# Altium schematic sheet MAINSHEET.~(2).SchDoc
size 594 x 420 mm; Scale: 1:1; Разраб.: Иванов; Обозначение документа: АБВГ.123456.001 Э3; Пров.: Петров; Утв.: Сидоров; Наименование организации: ОАО "Концерн "МПО-Гидроприбор"; Перв. применение: АБВГ.123456.000; Наименование изделия 1: Плата; Наименование изделия 2: Схема электрическая; Наименование изделия 3: принципиальная; Нач. отд.: Нач. отд.; Фамилия нач. отд.: Сидоров
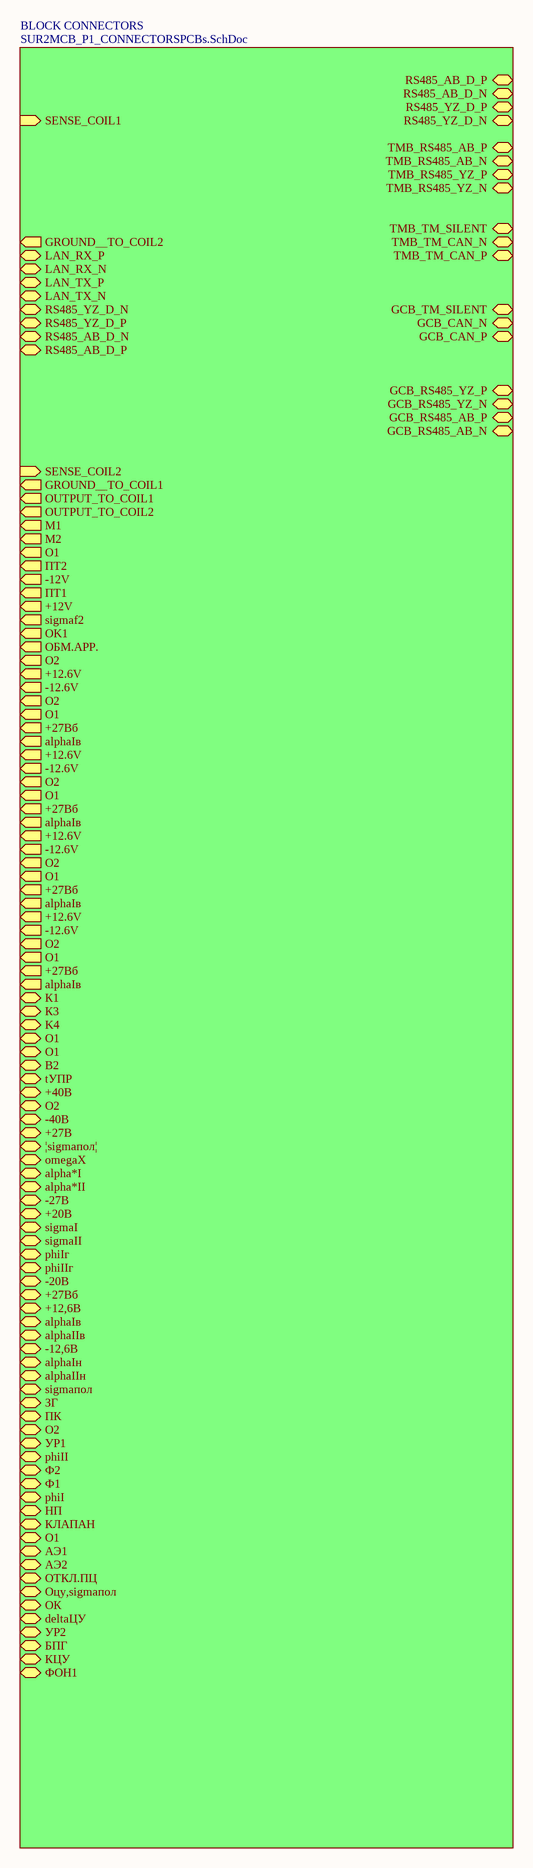
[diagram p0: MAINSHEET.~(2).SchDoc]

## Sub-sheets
BLOCK CONNECTORS = SUR2MCB_P1_CONNECTORSPCBs.SchDoc: RS485_AB_D_P (bidir), RS485_AB_D_N (bidir), SENSE_COIL1 (in), RS485_YZ_D_P (bidir), RS485_YZ_D_N (bidir), TMB_RS485_AB_P (bidir), TMB_TM_SILENT (bidir), TMB_TM_CAN_N (bidir), TMB_RS485_AB_N (bidir), GCB_CAN_N (bidir), GCB_TM_SILENT (bidir), GROUND__TO_COIL2 (out), LAN_RX_P (bidir), LAN_RX_N (bidir), LAN_TX_P (bidir), LAN_TX_N (bidir), RS485_YZ_D_N (bidir), RS485_YZ_D_P (bidir), RS485_AB_D_N (bidir), RS485_AB_D_P (bidir), GCB_CAN_P (bidir), GCB_RS485_YZ_N (bidir), TMB_TM_CAN_P (bidir), GCB_RS485_AB_P (bidir), TMB_RS485_YZ_P (bidir), TMB_RS485_YZ_N (bidir), GCB_RS485_YZ_P (bidir), GCB_RS485_AB_N (bidir), SENSE_COIL2 (in), GROUND__TO_COIL1 (out), OUTPUT_TO_COIL1 (out), OUTPUT_TO_COIL2 (out), M1 (out), M2 (out), O1 (out), ПТ2 (out), -12V (out), ПТ1 (out), +12V (out), sigmaf2 (out), OK1 (out), ОБМ.АРР. (out), O2 (out), +12.6V (out), -12.6V (out), O2 (out), O1 (out), +27Вб (out), alphaIв (out), +12.6V (out), -12.6V (out), O2 (out), O1 (out), +27Вб (out), alphaIв (out), +12.6V (out), -12.6V (out), O2 (out), O1 (out), +27Вб (out), alphaIв (out), +12.6V (out), -12.6V (out), O2 (out), O1 (out), +27Вб (out), alphaIв (out), К1 (bidir), К3 (bidir), K4 (bidir), O1 (bidir), O1 (bidir), B2 (bidir), tУПР (bidir), +40В (bidir), О2 (bidir), -40В (bidir), +27В (bidir), ¦sigmaпол¦ (bidir), omegaX (bidir), alpha*I (bidir), alpha*II (bidir), -27В (bidir), +20В (bidir), sigmaI (bidir), sigmaII (bidir), phiIг (bidir), phiIIг (bidir), -20В (bidir), +27Вб (bidir), +12,6В (bidir), alphaIв (bidir), alphaIIв (bidir), -12,6В (bidir), alphaIн (bidir), alphaIIн (bidir), sigmaпол (bidir), ЗГ (bidir), ПК (bidir), O2 (bidir), УР1 (bidir), phiII (bidir), Ф2 (bidir), Ф1 (bidir), phiI (bidir), НП (bidir), КЛАПАН (bidir), О1 (bidir), АЭ1 (bidir), АЭ2 (bidir), ОТКЛ.ПЦ (bidir), Оцу,sigmaпол (bidir), ОК (bidir), deltaЦУ (bidir), УР2 (bidir), БПГ (bidir), КЦУ (bidir), ФОН1 (bidir)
